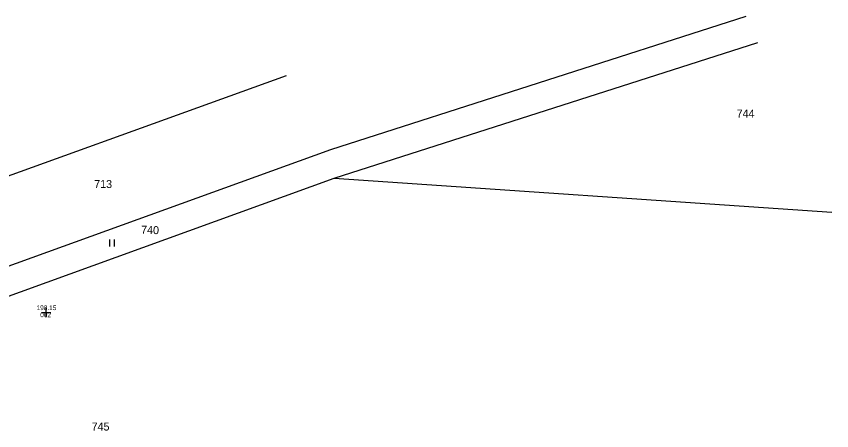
# Model space of a CAD drawing. Extents: x -706655 to -706193, y -1036183 to -1034979.
# Drawn here: x -706382.1 to -706295.5, y -1035226.1 to -1035182.1 of the extents above; entities that cross this region are included whole.
import ezdxf

# ---------------------------------------------------------------- set-up
doc = ezdxf.new("R2010")
doc.units = 0
for name, color, linetype in [('Hranice parcel', 7, 'Continuous'), ('křížky', 7, 'Continuous'), ('Parcelní čísla', 7, 'Continuous'), ('výšky', 7, 'Continuous'), ('Značky kultur', 7, 'Continuous'), ('čísla bodu', 7, 'Continuous')]:
    doc.layers.add(name, color=color, linetype=linetype)

msp = doc.modelspace()

# ---------------------------------------------------------------- linework, layer by layer
at = {"layer": 'Hranice parcel'}
msp.add_line((-706387.38, -1035213.42), (-706348.39, -1035199.33), dxfattribs=at)
for points in [[(-706388.41, -1035210.6), (-706348.72, -1035196.28), (-706304.613, -1035182.15)], [(-706348.39, -1035199.33), (-706303.391, -1035184.909)], [(-706393.32, -1035202.8), (-706353.44, -1035188.416)], [(-706348.39, -1035199.33), (-706295.531, -1035202.911)]]:
    msp.add_lwpolyline(points, dxfattribs=at)
at = {"layer": 'křížky'}
for p, q in [((-706379.47, -1035213.57), (-706378.47, -1035213.57)), ((-706378.97, -1035214.07), (-706378.97, -1035213.07)), ((-706378.97, -1035213.57), (-706378.97, -1035213.57))]:
    msp.add_line(p, q, dxfattribs=at)
at = {"layer": 'Značky kultur'}
for p, q in [((-706372.202, -1035206.58), (-706372.202, -1035205.83)), ((-706371.701, -1035206.58), (-706371.701, -1035205.83))]:
    msp.add_line(p, q, dxfattribs=at)
at = {"layer": 'čísla bodu'}
for p, q in [((-706379.47, -1035213.57), (-706378.47, -1035213.57)), ((-706378.97, -1035214.07), (-706378.97, -1035213.07)), ((-706378.97, -1035213.57), (-706378.97, -1035213.57))]:
    msp.add_line(p, q, dxfattribs=at)

# ---------------------------------------------------------------- texts
at = {"layer": 'Parcelní čísla'}
for s, p in [('744', (-706305.627, -1035192.885)), ('713', (-706373.866, -1035200.365)), ('745', (-706374.14, -1035226.095))]:
    msp.add_text(s, height=0.85, dxfattribs=at).set_placement(p)
msp.add_text('740', height=0.85, rotation=358, dxfattribs=at).set_placement((-706368.895, -1035205.201))
at = {"layer": 'výšky'}
msp.add_text('198.15', height=0.5, dxfattribs=at).set_placement((-706379.992, -1035213.32))
at = {"layer": 'čísla bodu'}
msp.add_text('002', height=0.5, dxfattribs=at).set_placement((-706379.604, -1035214.07))

doc.saveas('drawing.dxf')
